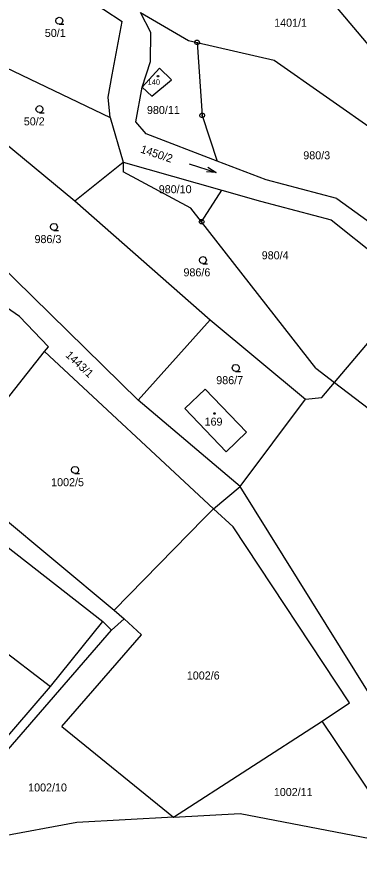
# Model space of a CAD drawing. Extents: x -850689 to -847910, y -1058374 to -1054747.
# Drawn here: x -849187.1 to -849114.6, y -1056427.2 to -1056250.1 of the extents above; entities that cross this region are included whole.
import ezdxf

# ---------------------------------------------------------------- set-up
doc = ezdxf.new("R2010")
doc.units = 0
for name, color, linetype in [('KN_HRANICE', 7, 'Continuous'), ('KN_KULTURY', 7, 'Continuous'), ('KN_MEZNIKY', 7, 'Continuous'), ('KN_PARCELY', 7, 'Continuous'), ('KN_STAVEBNI', 7, 'Continuous')]:
    doc.layers.add(name, color=color, linetype=linetype)

# ---------------------------------------------------------------- blocks, each defined once
blk = doc.blocks.new('304')
blk.add_lwpolyline([(0, 0), (-0.38, 0.1), (-0.65, 0.37), (-0.75, 0.74), (-0.65, 1.11), (-0.38, 1.38), (-0.01, 1.48), (0.36, 1.38), (0.63, 1.11), (0.73, 0.73), (0.63, 0.35), (0.36, 0.08), (-0.02, -0.02), (0.98, -0.02)])
blk = doc.blocks.new('802')
blk.add_line((-3, 0), (3, 0))
blk.add_lwpolyline([(1, 0.5), (3, 0), (1, -0.5)])
blk = doc.blocks.new('105')
blk.add_line((-0.12, 0), (0.12, 0))
blk.add_lwpolyline([(0.15, 0.48), (0.4, 0.3), (0.5, 0.01), (0.4, -0.28), (0.15, -0.46), (-0.16, -0.46), (-0.41, -0.28), (-0.51, 0.01), (-0.41, 0.3), (-0.16, 0.48), (0.15, 0.48)])
blk = doc.blocks.new('402')
blk.add_lwpolyline([(0.09, 0.15), (0.18, 0), (0.09, -0.15), (-0.09, -0.15), (-0.18, 0), (-0.09, 0.15), (0.09, 0.15)])

msp = doc.modelspace()

# ---------------------------------------------------------------- linework, layer by layer
at = {"layer": 'KN_HRANICE'}
for p, q in [((-849123.4, -1056243.38), (-849109.14, -1056260.33)), ((-849172.85, -1056245.8), (-849164.8, -1056251.16)), ((-849158.72, -1056253.46), (-849160.92, -1056249.26)), ((-849160.92, -1056249.26), (-849150.75, -1056255.14)), ((-849166.92, -1056262.43), (-849164.8, -1056251.16)), ((-849158.79, -1056259.59), (-849158.72, -1056253.46)), ((-849150.75, -1056255.14), (-849148.92, -1056255.56)), ((-849148.92, -1056255.56), (-849132.64, -1056259.34)), ((-849148.92, -1056255.56), (-849147.84, -1056271.04)), ((-849195.81, -1056257.87), (-849167.34, -1056271.45)), ((-849160.55, -1056265.07), (-849158.79, -1056259.59)), ((-849132.64, -1056259.34), (-849099.56, -1056282.53)), ((-849156.88, -1056261.06), (-849160.55, -1056265.07)), ((-849154.35, -1056263.5), (-849156.88, -1056261.06)), ((-849167.78, -1056267.19), (-849166.92, -1056262.43)), ((-849158.48, -1056266.96), (-849154.35, -1056263.5)), ((-849161.91, -1056272.4), (-849160.55, -1056265.07)), ((-849160.55, -1056265.07), (-849158.48, -1056266.96)), ((-849167.34, -1056271.45), (-849167.78, -1056267.19)), ((-849167.34, -1056271.45), (-849164.6, -1056280.95)), ((-849159.69, -1056274.96), (-849161.91, -1056272.4)), ((-849147.84, -1056271.04), (-849144.65, -1056280.72)), ((-849144.65, -1056280.72), (-849159.69, -1056274.96)), ((-849189.99, -1056276.6), (-849174.78, -1056289.12)), ((-849174.78, -1056289.12), (-849164.6, -1056280.95)), ((-849164.6, -1056280.95), (-849143.72, -1056286.9)), ((-849164.6, -1056280.95), (-849164.59, -1056283.02)), ((-849134.31, -1056284.69), (-849144.65, -1056280.72)), ((-849150.22, -1056290.7), (-849164.59, -1056283.02)), ((-849119.35, -1056288.63), (-849134.31, -1056284.69)), ((-849147.96, -1056293.59), (-849143.72, -1056286.9)), ((-849143.72, -1056286.9), (-849135.51, -1056289.24)), ((-849119.35, -1056288.63), (-849099.62, -1056302.96)), ((-849174.78, -1056289.12), (-849146.16, -1056314.38)), ((-849135.51, -1056289.24), (-849120.55, -1056293.17)), ((-849161.41, -1056331.37), (-849201.97, -1056291.61)), ((-849147.96, -1056293.59), (-849150.22, -1056290.7)), ((-849123.81, -1056324.58), (-849147.96, -1056293.59)), ((-849120.55, -1056293.17), (-849105.79, -1056304.92)), ((-849119.84, -1056327.63), (-849103.9, -1056308.71)), ((-849186.5, -1056313.66), (-849190.95, -1056310.59)), ((-849180.36, -1056320.1), (-849186.5, -1056313.66)), ((-849161.41, -1056331.37), (-849146.16, -1056314.38)), ((-849146.16, -1056314.38), (-849125.99, -1056331.15)), ((-849181.26, -1056321.09), (-849180.36, -1056320.1)), ((-849201.5, -1056346.7), (-849181.26, -1056321.09)), ((-849181.26, -1056321.09), (-849145.42, -1056354.4)), ((-849123.81, -1056324.58), (-849119.84, -1056327.63)), ((-849122.51, -1056330.8), (-849119.84, -1056327.63)), ((-849119.84, -1056327.63), (-849111.2, -1056334.22)), ((-849151.51, -1056333.16), (-849147.19, -1056329.03)), ((-849147.19, -1056329.03), (-849138.43, -1056338.18)), ((-849139.79, -1056349.71), (-849125.99, -1056331.15)), ((-849125.99, -1056331.15), (-849122.51, -1056330.8)), ((-849139.79, -1056349.71), (-849161.41, -1056331.37)), ((-849142.75, -1056342.31), (-849151.51, -1056333.16)), ((-849223.07, -1056335.94), (-849168.88, -1056378.32)), ((-849138.43, -1056338.18), (-849142.75, -1056342.31)), ((-849201.5, -1056346.7), (-849166.49, -1056375.89)), ((-849145.42, -1056354.4), (-849139.79, -1056349.71)), ((-849112.51, -1056393.58), (-849139.79, -1056349.71)), ((-849145.42, -1056354.4), (-849147.47, -1056356.49)), ((-849145.42, -1056354.4), (-849141.27, -1056358.26)), ((-849147.47, -1056356.49), (-849166.49, -1056375.89)), ((-849116.66, -1056395.53), (-849141.27, -1056358.26)), ((-849215.1, -1056365.17), (-849179.95, -1056392.09)), ((-849166.49, -1056375.89), (-849164.34, -1056377.76)), ((-849179.95, -1056392.09), (-849168.88, -1056378.32)), ((-849168.88, -1056378.32), (-849167.05, -1056380.13)), ((-849167.05, -1056380.13), (-849164.34, -1056377.76)), ((-849160.67, -1056381.14), (-849164.34, -1056377.76)), ((-849207.62, -1056426.96), (-849167.05, -1056380.13)), ((-849177.57, -1056400.57), (-849160.67, -1056381.14)), ((-849210.21, -1056427.21), (-849179.95, -1056392.09)), ((-849122.42, -1056399.43), (-849116.66, -1056395.53)), ((-849153.92, -1056419.76), (-849122.42, -1056399.43)), ((-849104.83, -1056425.71), (-849122.42, -1056399.43)), ((-849177.57, -1056400.57), (-849153.92, -1056419.76)), ((-849153.92, -1056419.76), (-849174.42, -1056420.91)), ((-849153.92, -1056419.76), (-849139.78, -1056418.98)), ((-849139.78, -1056418.98), (-849104.83, -1056425.71)), ((-849174.42, -1056420.91), (-849207.62, -1056426.96))]:
    msp.add_line(p, q, dxfattribs=at)
at = {"layer": 'KN_STAVEBNI'}
for p, q in [((-849156.88, -1056261.06), (-849160.55, -1056265.07)), ((-849154.35, -1056263.5), (-849156.88, -1056261.06)), ((-849158.48, -1056266.96), (-849154.35, -1056263.5)), ((-849160.55, -1056265.07), (-849158.48, -1056266.96)), ((-849151.51, -1056333.16), (-849147.19, -1056329.03)), ((-849147.19, -1056329.03), (-849138.43, -1056338.18)), ((-849142.75, -1056342.31), (-849151.51, -1056333.16)), ((-849138.43, -1056338.18), (-849142.75, -1056342.31))]:
    msp.add_line(p, q, dxfattribs=at)

# ---------------------------------------------------------------- block references
at = {"layer": 'KN_KULTURY'}
for name, p in [('304', (-849178.09, -1056251.71)), ('402', (-849157.21, -1056262.73)), ('304', (-849182.3, -1056270.45)), ('304', (-849179.22, -1056295.4)), ('304', (-849147.68, -1056302.45)), ('304', (-849140.74, -1056325.3)), ('402', (-849145.24, -1056334.2)), ('304', (-849174.77, -1056346.92))]:
    msp.add_blockref(name, p, dxfattribs=at)
at = {"layer": 'KN_KULTURY', "rotation": -17.944195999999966}
msp.add_blockref('802', (-849147.75, -1056282.2), dxfattribs=at)
at = {"layer": 'KN_MEZNIKY', "rotation": 0.687549}
for p in [(-849148.92, -1056255.56), (-849147.84, -1056271.04)]:
    msp.add_blockref('105', p, dxfattribs=at)
at = {"layer": 'KN_MEZNIKY'}
msp.add_blockref('105', (-849147.96, -1056293.59), dxfattribs=at)

# ---------------------------------------------------------------- texts
at = {"layer": 'KN_PARCELY'}
for s, height, p in [('1401/1', 1.7, (-849132.61, -1056252.24)), ('50/1', 1.7, (-849181.17, -1056254.41)), ('140', 1.14, (-849159.4, -1056264.54)), ('980/11', 1.7, (-849159.54, -1056270.74)), ('50/2', 1.7, (-849185.62, -1056273.15)), ('980/3', 1.7, (-849126.44, -1056280.34)), ('980/10', 1.7, (-849157.04, -1056287.53)), ('986/3', 1.7, (-849183.35, -1056298.1)), ('980/4', 1.7, (-849135.24, -1056301.53)), ('986/6', 1.7, (-849151.81, -1056305.15)), ('986/7', 1.7, (-849144.87, -1056328)), ('169', 1.7, (-849147.34, -1056336.79)), ('1002/5', 1.7, (-849179.83, -1056349.62)), ('1002/6', 1.7, (-849151.1, -1056390.59)), ('1002/10', 1.7, (-849184.7, -1056414.32)), ('1002/11', 1.7, (-849132.68, -1056415.29))]:
    msp.add_text(s, height=height, dxfattribs=at).set_placement(p)
for s, rotation, p in [('1450/2', 341.54, (-849161.04, -1056278.88)), ('1443/1', 317.189, (-849176.92, -1056322.03))]:
    msp.add_text(s, height=1.7, rotation=rotation, dxfattribs=at).set_placement(p)

doc.saveas('drawing.dxf')
